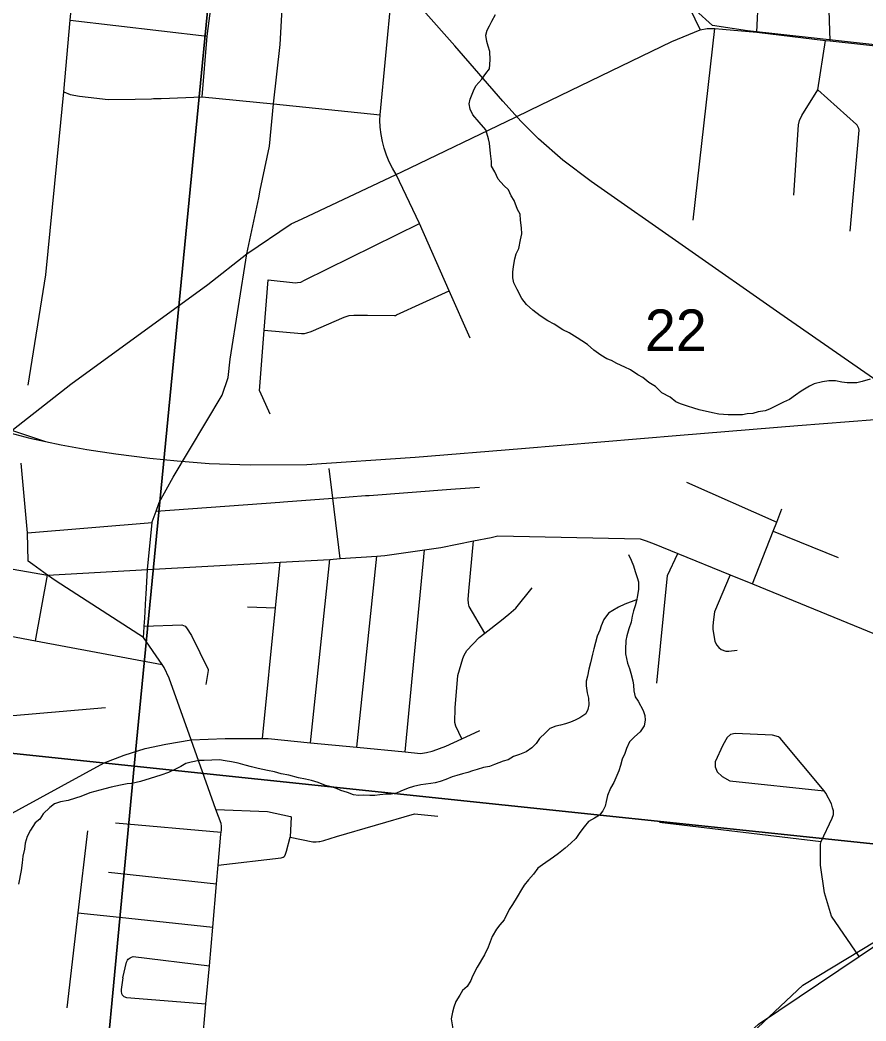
# Model space of a CAD drawing. Extents: x 0 to 34, y 0 to 22.
# Drawn here: x 2.735 to 3.161, y 18.402 to 18.905 of the extents above; entities that cross this region are included whole.
import ezdxf

# ---------------------------------------------------------------- set-up
doc = ezdxf.new("R2010")
doc.units = 0
for name, color, linetype in [('GM_X_City_Street', 7, 'Continuous'), ('GM_X_County_Road', 7, 'Continuous'), ('GM_X_Minor_River', 7, 'Continuous'), ('GM_X_Rail_Line', 7, 'Continuous'), ('GM_X_Section', 7, 'Continuous'), ('GM_X_Section_Text', 7, 'Continuous')]:
    doc.layers.add(name, color=color, linetype=linetype)

msp = doc.modelspace()

# ---------------------------------------------------------------- linework, layer by layer
at = {"layer": 'GM_X_City_Street'}
for p, q in [((3.10614, 18.89922), (3.10805, 18.9392)), ((2.76047, 18.90517), (2.82944, 18.89717)), ((3.07414, 18.80465), (3.08501, 18.90111)), ((2.85586, 18.71865), (2.86107, 18.70708)), ((3.07086, 18.67274), (3.11623, 18.65262)), ((2.73901, 18.6472), (2.80176, 18.65245)), ((3.11446, 18.64809), (3.1472, 18.6348)), ((2.92907, 18.53701), (2.93893, 18.63863)), ((2.8814, 18.54162), (2.89119, 18.63391)), ((2.90482, 18.53935), (2.91479, 18.63552)), ((2.74303, 18.59298), (2.74896, 18.626)), ((2.84974, 18.61), (2.86383, 18.60948)), ((2.71122, 18.55351), (2.77828, 18.55933)), ((2.7833, 18.50131), (2.83647, 18.49655)), ((3.05712, 18.5017), (3.13852, 18.49196)), ((2.77981, 18.47652), (2.8342, 18.47062))]:
    msp.add_line(p, q, dxfattribs=at)
for points in [[(3.14305, 18.89478), (3.1424, 18.91549), (3.14995, 18.92157), (3.15481, 18.92581), (3.15647, 18.92778), (3.15728, 18.92891), (3.15756, 18.92972), (3.16033, 18.9496), (3.16107, 18.96122), (3.16102, 18.96212), (3.15866, 18.96617), (3.14915, 18.98085), (3.15071, 18.99879)], [(2.82687, 18.86671), (2.82944, 18.89717), (2.83358, 18.92937), (2.83576, 18.95839), (2.83775, 18.99057), (2.83822, 18.99359)], [(2.92458, 18.82765), (2.92276, 18.83077), (2.92116, 18.834), (2.91978, 18.83733), (2.91862, 18.84075), (2.91769, 18.84423), (2.91699, 18.84777), (2.91653, 18.85135), (2.91631, 18.85496), (2.91651, 18.85759), (2.92226, 18.91754)], [(3.15318, 18.79914), (3.15765, 18.84984), (3.15755, 18.85075), (3.15727, 18.85142), (3.15678, 18.85237), (3.15641, 18.85282), (3.13691, 18.87024), (3.14083, 18.89494)], [(3.12477, 18.81718), (3.12717, 18.85264), (3.12771, 18.85472), (3.12881, 18.85734), (3.13691, 18.87024)], [(2.7572, 18.86913), (2.76049, 18.86786), (2.76517, 18.86697), (2.76955, 18.86647), (2.77958, 18.86533), (2.79311, 18.86541), (2.80149, 18.86571), (2.80244, 18.86576), (2.80339, 18.86579), (2.80435, 18.8658), (2.8053, 18.8658), (2.80626, 18.86578), (2.82687, 18.86671), (2.86284, 18.86315)], [(2.96188, 18.74519), (2.95131, 18.76901), (2.93631, 18.80285), (2.92458, 18.82765)], [(2.86016, 18.77456), (2.87398, 18.77305), (2.87485, 18.77317), (2.87661, 18.77343), (2.87838, 18.77444), (2.93631, 18.80285)], [(2.85586, 18.71865), (2.85821, 18.74917), (2.86016, 18.77456)], [(2.85821, 18.74917), (2.87692, 18.74751), (2.8785, 18.74758), (2.87963, 18.74782), (2.88188, 18.74852), (2.89839, 18.75585), (2.90096, 18.75659), (2.90335, 18.75686), (2.91018, 18.75686), (2.92379, 18.75665), (2.92422, 18.75667), (2.92485, 18.75691), (2.95131, 18.76901)], [(2.89637, 18.63427), (2.89264, 18.66474), (2.89083, 18.6796)], [(2.91094, 18.6661), (2.9522, 18.66916), (2.96657, 18.67023)], [(2.86794, 18.66291), (2.89264, 18.66474), (2.90908, 18.66596), (2.91094, 18.6661)], [(2.80369, 18.65814), (2.86597, 18.66276), (2.86794, 18.66291)], [(3.10405, 18.6215), (3.11446, 18.64809), (3.11623, 18.65262), (3.11887, 18.65934)], [(2.9693, 18.59677), (2.96136, 18.61025), (2.96114, 18.6109), (2.96096, 18.61183), (2.96087, 18.61368), (2.96117, 18.61785), (2.9636, 18.64316)], [(3.05583, 18.57165), (3.06116, 18.62584), (3.06637, 18.63691)], [(2.8573, 18.54367), (2.86383, 18.60948), (2.86612, 18.63252)], [(3.09276, 18.62612), (3.08491, 18.60743), (3.08433, 18.60368), (3.08408, 18.60044), (3.08408, 18.59852), (3.085, 18.59279), (3.08586, 18.59088), (3.08707, 18.58946), (3.08827, 18.58854), (3.09053, 18.58773), (3.09214, 18.58772), (3.09623, 18.58816)], [(2.95766, 18.5436), (2.95458, 18.55), (2.95414, 18.55175), (2.95433, 18.55915), (2.9557, 18.57545), (2.9582, 18.58393), (2.95889, 18.5857), (2.96021, 18.58806), (2.96645, 18.59453), (2.9693, 18.59677), (2.97769, 18.60335), (2.98138, 18.60629), (2.98487, 18.60942), (2.99311, 18.61964)], [(2.68538, 18.60385), (2.74303, 18.59298), (2.75825, 18.59011), (2.80683, 18.58095)], [(2.79778, 18.60027), (2.81664, 18.60089), (2.81832, 18.60029), (2.81908, 18.59949), (2.82163, 18.59563), (2.82992, 18.57849), (2.82996, 18.57801), (2.82877, 18.57093)], [(2.93889, 18.53656), (2.93991, 18.5367), (2.94275, 18.53743), (2.94325, 18.53761), (2.94965, 18.5399), (2.95766, 18.5436), (2.96675, 18.5478)], [(2.82135, 18.54304), (2.83851, 18.54369), (2.8573, 18.54367), (2.86015, 18.54367), (2.8814, 18.54162), (2.90482, 18.53935), (2.92907, 18.53701), (2.93684, 18.53626), (2.93889, 18.53656)], [(3.15772, 18.43408), (3.14385, 18.45439), (3.14035, 18.46607), (3.13823, 18.48), (3.13824, 18.49062), (3.13852, 18.49196), (3.14413, 18.50359), (3.14473, 18.50542), (3.14479, 18.50737), (3.14436, 18.50884), (3.14374, 18.51082), (3.14102, 18.51621), (3.14005, 18.51738), (3.11794, 18.54396), (3.11705, 18.54458), (3.11403, 18.54542), (3.09525, 18.54629), (3.093, 18.54579), (3.09122, 18.54431), (3.08903, 18.54038), (3.08522, 18.53193), (3.08516, 18.52952), (3.08623, 18.52696), (3.08883, 18.52462), (3.09257, 18.52242), (3.14005, 18.51738)], [(2.83375, 18.50796), (2.85976, 18.50702), (2.87139, 18.50453), (2.87167, 18.50426), (2.8712, 18.49417)], [(2.8712, 18.49417), (2.88271, 18.49176), (2.88425, 18.49167), (2.88573, 18.49188), (2.88623, 18.49198), (2.88824, 18.49237), (2.89456, 18.49448), (2.93377, 18.50576), (2.94551, 18.50468)], [(2.76915, 18.49732), (2.76438, 18.45603), (2.75885, 18.40813)], [(2.83501, 18.47995), (2.86675, 18.48365), (2.86774, 18.48402), (2.86815, 18.48432), (2.86849, 18.48474), (2.86883, 18.48548), (2.86931, 18.487), (2.8712, 18.49417)], [(2.76438, 18.45603), (2.78527, 18.45382), (2.83227, 18.44885)], [(2.78702, 18.42326), (2.7888, 18.43117), (2.78891, 18.43158), (2.78928, 18.43227), (2.78973, 18.43276), (2.79066, 18.43344), (2.79126, 18.43378), (2.79219, 18.43398), (2.83053, 18.42935)], [(2.78702, 18.42326), (2.78609, 18.4174), (2.78609, 18.41643), (2.78637, 18.41539), (2.78665, 18.41472), (2.78755, 18.41388), (2.7889, 18.41333), (2.82882, 18.41016)]]:
    msp.add_lwpolyline(points, dxfattribs=at)
at = {"layer": 'GM_X_County_Road'}
for p, q in [((3.06622, 18.92409), (3.0777, 18.90045)), ((2.86284, 18.86315), (2.91651, 18.85759))]:
    msp.add_line(p, q, dxfattribs=at)
for points in [[(2.75487, 18.84527), (2.7572, 18.86913), (2.76047, 18.90517), (2.76353, 18.93623), (2.76465, 18.98056), (2.76489, 18.98873), (2.76527, 18.9938)], [(2.85619, 18.81969), (2.86076, 18.84189), (2.86284, 18.86315), (2.86617, 18.89307), (2.86793, 18.92309), (2.86755, 18.92741), (2.86682, 18.93017), (2.86434, 18.93634)], [(2.99193, 18.85995), (3.06348, 18.89453), (3.0777, 18.90045), (3.08115, 18.90111), (3.08501, 18.90111), (3.08888, 18.90078), (3.10614, 18.89922), (3.14083, 18.89494), (3.14305, 18.89478), (3.21324, 18.88712), (3.29003, 18.87875), (3.29293, 18.87846)], [(2.87729, 18.80534), (2.92458, 18.82765), (2.92743, 18.82897), (2.98473, 18.85647), (2.99193, 18.85995)], [(2.73929, 18.72153), (2.74818, 18.77702), (2.75487, 18.84527)], [(2.7987, 18.61641), (2.79942, 18.6288), (2.80176, 18.65245), (2.8018, 18.65282), (2.80369, 18.65814), (2.80521, 18.66244), (2.81229, 18.67521), (2.837, 18.71651), (2.84002, 18.72537), (2.84096, 18.73467), (2.84942, 18.78759), (2.85542, 18.8159), (2.85619, 18.81969)], [(2.7608, 18.7221), (2.82969, 18.7723), (2.84942, 18.78759), (2.8717, 18.80271), (2.87729, 18.80534)], [(2.65789, 18.64332), (2.68337, 18.66157), (2.7608, 18.7221)], [(2.74042, 18.63213), (2.73927, 18.63301), (2.73901, 18.6472), (2.7358, 18.6823)], [(2.65789, 18.64332), (2.66634, 18.64031), (2.74896, 18.626), (2.79942, 18.6288), (2.86612, 18.63252), (2.89119, 18.63391), (2.89637, 18.63427), (2.91479, 18.63552), (2.91897, 18.6358), (2.93893, 18.63863), (2.94714, 18.63979), (2.9636, 18.64316), (2.97249, 18.64497), (2.97573, 18.64567), (3.04745, 18.64421), (3.05047, 18.6432), (3.05443, 18.64179), (3.06637, 18.63691), (3.09276, 18.62612), (3.10405, 18.6215), (3.17572, 18.5922)], [(2.79745, 18.59458), (2.75333, 18.62288), (2.74896, 18.626), (2.74158, 18.63125), (2.74042, 18.63213)], [(2.79801, 18.60429), (2.79858, 18.61434), (2.7987, 18.61641)], [(2.82691, 18.38871), (2.82882, 18.41016), (2.83053, 18.42935), (2.83227, 18.44885), (2.8342, 18.47062), (2.83501, 18.47995), (2.83635, 18.49554), (2.83647, 18.49655), (2.8366, 18.49765), (2.83662, 18.49969), (2.83643, 18.50102), (2.83375, 18.50796), (2.82135, 18.54304), (2.81035, 18.57418), (2.80779, 18.57955), (2.80683, 18.58095), (2.79745, 18.59458), (2.79775, 18.59988), (2.79778, 18.60027), (2.79801, 18.60429)], [(2.66096, 18.43403), (2.66184, 18.4352), (2.67278, 18.44986), (2.70047, 18.48693), (2.70378, 18.48991), (2.71069, 18.49489), (2.7346, 18.50797), (2.77764, 18.53152), (2.78758, 18.53531), (2.79828, 18.5387), (2.80857, 18.54096), (2.82135, 18.54304)], [(3.02641, 18.26549), (3.02909, 18.27021), (3.09743, 18.3905), (3.10073, 18.39404), (3.1071, 18.39999), (3.15772, 18.43408), (3.22018, 18.47615), (3.22496, 18.47881), (3.23107, 18.48122), (3.23726, 18.48341), (3.24217, 18.48445), (3.25301, 18.48517), (3.29974, 18.48909), (3.30984, 18.49013), (3.31345, 18.4907), (3.315, 18.49113), (3.31706, 18.49193), (3.31901, 18.49301)]]:
    msp.add_lwpolyline(points, dxfattribs=at)
at = {"layer": 'GM_X_Minor_River'}
for points in [[(2.96352, 18.86965), (2.96476, 18.87226), (2.96774, 18.87556), (2.96975, 18.87833), (2.97156, 18.88072), (2.97193, 18.88527), (2.97171, 18.88946), (2.97087, 18.89216), (2.9702, 18.89447), (2.96976, 18.89772), (2.97042, 18.90016), (2.97165, 18.90239), (2.9727, 18.90482), (2.97454, 18.90816)], [(3.1632, 18.7245), (3.15917, 18.72334), (3.15648, 18.72269), (3.1542, 18.72279), (3.15173, 18.7227), (3.14908, 18.723), (3.14588, 18.7237), (3.14246, 18.72366), (3.13921, 18.72322), (3.13499, 18.72226), (3.13266, 18.72102), (3.12857, 18.71853), (3.12565, 18.71656), (3.12271, 18.7144), (3.11962, 18.71301), (3.11264, 18.7095), (3.11032, 18.70864), (3.10689, 18.70822), (3.10419, 18.70738), (3.10133, 18.70712), (3.09904, 18.70664), (3.09599, 18.70658), (3.09181, 18.70656), (3.08708, 18.70695), (3.08387, 18.70765), (3.07709, 18.70907), (3.07446, 18.70994), (3.07128, 18.71103), (3.06771, 18.71213), (3.06547, 18.71317), (3.06252, 18.71557), (3.05843, 18.71764), (3.05513, 18.72082), (3.05179, 18.72286), (3.04885, 18.72545), (3.04624, 18.7267), (3.04254, 18.72933), (3.03975, 18.73058), (3.03564, 18.73247), (3.03304, 18.7339), (3.0306, 18.73477), (3.02763, 18.7366), (3.02412, 18.73922), (3.021, 18.74201), (3.01804, 18.74384), (3.01582, 18.74545), (3.01173, 18.7479), (3.00856, 18.74937), (3.00412, 18.75221), (3.00095, 18.75386), (2.99706, 18.7565), (2.99337, 18.75931), (2.99025, 18.7621), (2.98791, 18.76524), (2.98561, 18.76971), (2.98384, 18.77301), (2.98337, 18.7755), (2.98329, 18.77836), (2.9836, 18.7812), (2.98432, 18.78516), (2.98499, 18.7876), (2.98643, 18.79039), (2.98717, 18.79473), (2.98786, 18.79775), (2.98779, 18.80079), (2.98718, 18.80462), (2.98711, 18.80766), (2.98568, 18.81), (2.98396, 18.81444), (2.98253, 18.81678), (2.98113, 18.81988), (2.97875, 18.82207), (2.97602, 18.82523), (2.97427, 18.82891), (2.97267, 18.83183), (2.97257, 18.83411), (2.97216, 18.83812), (2.9716, 18.84328), (2.97112, 18.84558), (2.96978, 18.85001), (2.96632, 18.85395), (2.96324, 18.85769), (2.96183, 18.86041), (2.96136, 18.86309), (2.96184, 18.86554), (2.96352, 18.86965)], [(3.04154, 18.63642), (3.04295, 18.63351), (3.04416, 18.63061), (3.045, 18.62772), (3.04603, 18.62483), (3.0467, 18.62252), (3.04655, 18.61891), (3.04605, 18.6157), (3.04556, 18.61306), (3.04489, 18.61043), (3.04403, 18.60799), (3.04336, 18.60536), (3.04286, 18.60234), (3.04178, 18.59896), (3.04069, 18.5954), (3.04022, 18.59313), (3.04004, 18.58858), (3.04014, 18.58629), (3.0411, 18.58169), (3.04213, 18.57899), (3.0428, 18.57668), (3.04379, 18.57284), (3.04408, 18.57054), (3.04434, 18.56768), (3.04499, 18.5648), (3.04642, 18.56246), (3.04889, 18.5578), (3.04975, 18.55529), (3.05004, 18.553), (3.04954, 18.55017), (3.04752, 18.54702), (3.04458, 18.54467), (3.04201, 18.54212), (3.04054, 18.53876), (3.03968, 18.53613), (3.03843, 18.53333), (3.03754, 18.53014), (3.03668, 18.52751), (3.03563, 18.52508), (3.03416, 18.52153), (3.03254, 18.51875), (3.03106, 18.51501), (3.03037, 18.512), (3.0299, 18.50974), (3.02866, 18.50732), (3.02706, 18.5051), (3.02453, 18.50369), (3.02142, 18.50191), (3.01923, 18.49934), (3.01702, 18.4964), (3.01501, 18.49344), (3.01263, 18.49106), (3.00968, 18.48853), (3.00634, 18.48581), (3.0038, 18.48402), (2.99834, 18.48025), (2.99598, 18.47845), (2.99378, 18.4755), (2.99119, 18.47257), (2.989, 18.47), (2.98777, 18.46777), (2.98554, 18.46406), (2.9831, 18.46017), (2.98149, 18.45776), (2.979, 18.45254), (2.97681, 18.44997), (2.9752, 18.44776), (2.97297, 18.44405), (2.97086, 18.43882), (2.969, 18.4349), (2.96533, 18.42859), (2.96306, 18.42412), (2.96221, 18.42188), (2.96039, 18.41891), (2.95803, 18.41692), (2.9566, 18.41451), (2.95458, 18.41136), (2.95371, 18.40854), (2.95304, 18.4061), (2.95234, 18.40271), (2.95323, 18.39659)], [(3.04564, 18.61351), (3.0398, 18.6114), (3.0365, 18.60983), (3.03378, 18.60823), (3.03145, 18.60681), (3.02923, 18.60367), (3.02778, 18.60049), (3.02712, 18.59824), (3.02586, 18.59525), (3.02409, 18.58886), (3.02341, 18.58623), (3.02248, 18.5819), (3.0216, 18.5787), (3.02089, 18.57512), (3.02022, 18.57268), (3.02031, 18.5702), (3.02075, 18.56676), (3.0214, 18.56407), (3.02165, 18.56064), (3.02118, 18.55838), (3.02014, 18.55614), (3.01702, 18.55418), (3.01469, 18.55295), (3.01237, 18.5519), (3.00987, 18.55106), (3.00737, 18.5504), (3.00507, 18.54992), (3.00198, 18.54872), (2.99981, 18.54653), (2.99685, 18.5438), (2.99504, 18.54122), (2.99286, 18.53903), (2.99012, 18.53705), (2.98665, 18.53567), (2.98376, 18.53465), (2.98104, 18.53306), (2.97854, 18.5324), (2.9741, 18.53068), (2.97159, 18.52965), (2.96853, 18.5292), (2.96545, 18.52819), (2.96296, 18.52753), (2.96064, 18.52668), (2.95796, 18.52603), (2.95507, 18.5252), (2.95277, 18.52454), (2.94967, 18.52314), (2.94678, 18.52212), (2.94429, 18.52147), (2.942, 18.52118), (2.93951, 18.52071), (2.93703, 18.52044), (2.93338, 18.51964), (2.93069, 18.5188), (2.92702, 18.51724), (2.9247, 18.5162), (2.92202, 18.51574), (2.91955, 18.51565), (2.91631, 18.51541), (2.91383, 18.51513), (2.91135, 18.51504), (2.90832, 18.51517), (2.90565, 18.51509), (2.9032, 18.51538), (2.90002, 18.51665), (2.89682, 18.51755), (2.89458, 18.51859), (2.89196, 18.51946), (2.88894, 18.52015), (2.88539, 18.52163), (2.88201, 18.52253), (2.87899, 18.52323), (2.87541, 18.52395), (2.87052, 18.52529), (2.86675, 18.52602), (2.86337, 18.52692), (2.85979, 18.52764), (2.85507, 18.52859), (2.85169, 18.52949), (2.84849, 18.53039), (2.84511, 18.53129), (2.84172, 18.532), (2.83851, 18.53251), (2.83568, 18.53301), (2.82788, 18.53276), (2.8254, 18.53268), (2.82138, 18.53189), (2.8187, 18.53124), (2.81616, 18.52964), (2.81383, 18.52841), (2.80997, 18.52666), (2.80611, 18.5253), (2.80073, 18.52363), (2.79592, 18.52212), (2.79151, 18.52116), (2.78922, 18.52087), (2.78577, 18.52026), (2.78117, 18.51931), (2.77791, 18.51849), (2.77042, 18.51633), (2.76579, 18.51462)], [(2.76579, 18.51462), (2.7631, 18.51378), (2.75944, 18.51261), (2.75561, 18.51181), (2.75253, 18.5108), (2.75018, 18.509), (2.74682, 18.50591), (2.7452, 18.50312), (2.74284, 18.50132), (2.74042, 18.49762), (2.73877, 18.49446), (2.73788, 18.49107), (2.73738, 18.48805), (2.73667, 18.48447), (2.73635, 18.48125), (2.73582, 18.47728), (2.73441, 18.4705)]]:
    msp.add_lwpolyline(points, dxfattribs=at)
at = {"layer": 'GM_X_Rail_Line'}
for points in [[(3.60814, 18.84411), (3.10148, 18.89993), (3.08381, 18.90261), (3.06684, 18.91815), (3.02008, 19.01178), (3.00463, 19.02884), (2.98028, 19.04141), (2.95907, 19.04455), (2.93237, 19.04848), (2.86797, 19.05398), (2.84205, 19.04376), (2.82869, 19.02805), (2.82778, 19.02696)], [(3.17493, 18.71811), (3.11781, 18.7577), (3.02284, 18.82401), (3.00855, 18.83475), (2.99625, 18.84548), (2.98749, 18.85424), (2.97832, 18.86446), (2.95413, 18.8923), (2.86525, 18.99268)], [(2.22194, 18.89744), (2.32203, 18.85562), (2.35555, 18.84242), (2.41227, 18.81982), (2.47923, 18.79312), (2.58725, 18.75017), (2.64977, 18.72516), (2.67327, 18.71624), (2.69816, 18.70721), (2.72763, 18.69818), (2.74019, 18.69494), (2.75593, 18.69147), (2.7689, 18.68915), (2.78337, 18.68695), (2.80051, 18.68475), (2.8144, 18.68348), (2.83049, 18.68209), (2.8511, 18.68151), (2.87954, 18.68169), (2.93418, 18.68536), (2.98773, 18.68977), (3.06761, 18.69633), (3.12688, 18.70119), (3.19154, 18.70632)], [(2.72126, 18.70195), (2.73045, 18.69905), (2.7481, 18.6932)], [(3.02085, 18.25134), (3.10377, 18.3956), (3.1294, 18.41953), (3.21763, 18.47294), (3.23651, 18.48126), (3.25222, 18.48441), (3.25323, 18.48449)]]:
    msp.add_lwpolyline(points, dxfattribs=at)
at = {"layer": 'GM_X_Section'}
for points in [[(2.33614, 19.08597), (2.84187, 19.03609), (2.79274, 18.52978), (2.28405, 18.58331)], [(2.84187, 19.03609), (3.33585, 18.97757), (3.29405, 18.47716), (2.79274, 18.52978)], [(2.28405, 18.58331), (2.79274, 18.52978), (2.7454, 18.02721), (2.23892, 18.07747)], [(2.79274, 18.52978), (3.29405, 18.47716), (3.2415, 17.96998), (2.7454, 18.02721)]]:
    msp.add_lwpolyline(points, close=True, dxfattribs=at)

# ---------------------------------------------------------------- texts
at = {"layer": 'GM_X_Section_Text'}
msp.add_text('22', height=0.020928, rotation=0, dxfattribs=at).set_placement((3.04984, 18.73872))

doc.saveas('drawing.dxf')
